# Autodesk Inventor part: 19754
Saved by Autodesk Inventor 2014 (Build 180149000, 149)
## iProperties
Shininess: 64.0
Length Units: 11272
Angle Units: 11279
Time Units: 11290
Mass Units: 11286
Length Display Precision: 3
Angle Display Precision: 2
Company: Autodesk, Inc.
Created: 2001-12
Part Number: 19754
Material: Stainless Steel, 440C
Description: FITTING; MC-G20-SS
Document SubType Name: Modeling
Designer: Autodesk, Inc.
Density: 7.75 g/cm^3
Mass: 391.381 g
Surface Area: 84.0954 cm^2
Volume: 50.5007 cm^3
Appearance: Stainless Steel
Density: 7.75
Volumn: 1.1899929784618444
Area: 7.049002142317107
PropertySet Name: Model Information
Control State: 0
Master: False
Checked Out: True
Last Check In By: JT
Last Check In Date: 2003-06-20
Title: FITTING; MC-G20-SS
Author: Autodesk, Inc.
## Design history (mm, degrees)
derived "MC-G.ipt"
body "Solid1"
tag "TaggingFeature2"
feature "Solid1::MC-G.ipt" dims "ScaleForDerivedMember" = 10
